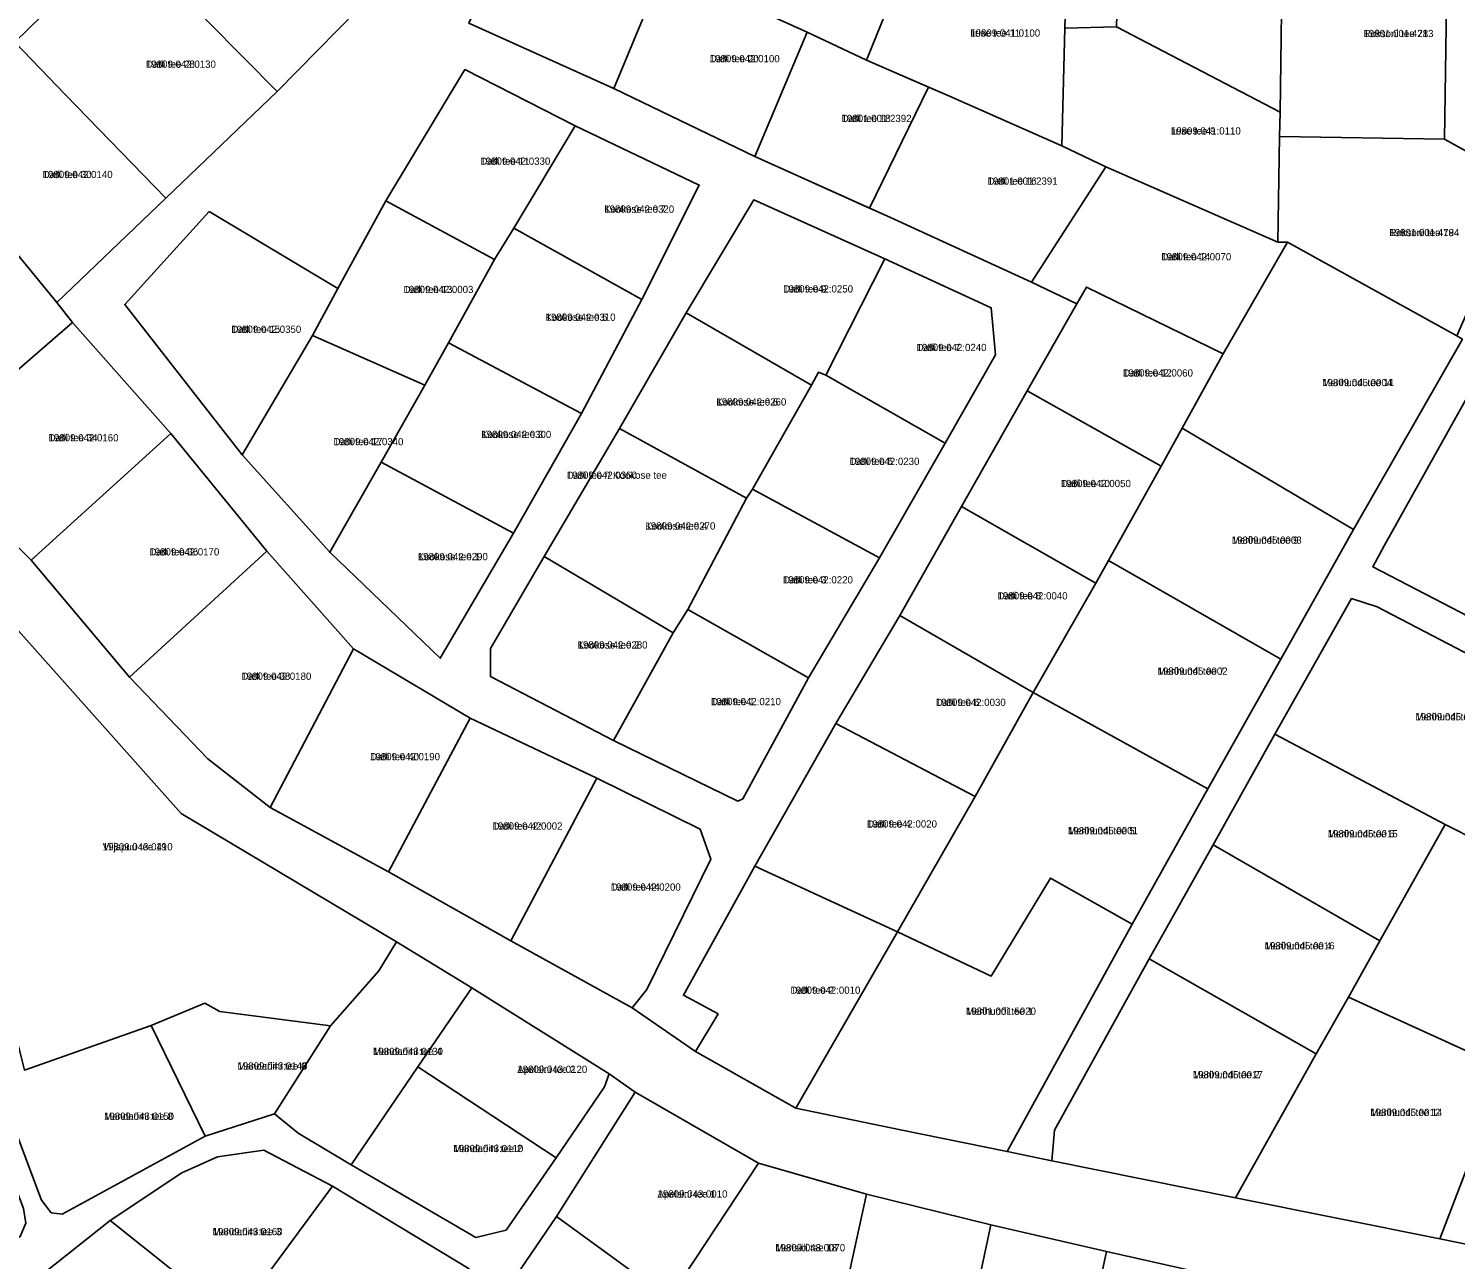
# Model space of a CAD drawing. Extents: x 516875 to 535633, y 6574491 to 6593094.
# Drawn here: x 522001.4 to 522297.3, y 6588394.7 to 6588649.8 of the extents above; entities that cross this region are included whole.
import ezdxf

# ---------------------------------------------------------------- set-up
doc = ezdxf.new("R2010")
doc.units = 0
for name, color, linetype in [('L_AADRESS', 7, 'Continuous'), ('PIIR', 7, 'Continuous'), ('TUNNUS', 7, 'Continuous')]:
    doc.layers.add(name, color=color, linetype=linetype)

msp = doc.modelspace()

# ---------------------------------------------------------------- linework, layer by layer
at = {"layer": 'PIIR'}
for points in [[(522311.5, 6588617.76), (522295, 6588626.88), (522295.65, 6588668.99), (522296.28, 6588711.24), (522296.84, 6588751.11), (522297, 6588762.2), (522296.53, 6588764.76), (522295.97, 6588767.58), (522312.6, 6588763.41)], [(522092.72, 6588650.96), (522122.81, 6588637.37), (522152.05, 6588623.29), (522180.16, 6588610.65), (522209.42, 6588597.23), (522218.77, 6588592.78), (522208.49, 6588574.71), (522194.85, 6588550.77), (522182.06, 6588528.21), (522168.79, 6588505.82), (522152.01, 6588476.24), (522137.21, 6588449.49), (522144.41, 6588445.6), (522139.74, 6588437.81), (522126.56, 6588446.88), (522129.6, 6588450.7), (522142.91, 6588477.69), (522140.67, 6588483.89), (522119.24, 6588494.45), (522092.99, 6588506.9), (522068.78, 6588521.27), (522050.84, 6588541.53), (522030.93, 6588565.87), (522010.56, 6588588.92), (522007.33, 6588593.08), (522029.9, 6588614.7), (522052.99, 6588636.81), (522073.91, 6588658.13)], [(522318.7, 6588510.33), (522281.07, 6588529.99), (522275.77, 6588531.67), (522259.83, 6588503.6), (522247.05, 6588480.62), (522233.76, 6588457.02), (522214.14, 6588421.5), (522213.58, 6588415.18), (522204.36, 6588417.09), (522230.26, 6588464.24), (522245.94, 6588492.24), (522261.06, 6588519.1), (522276.18, 6588546), (522298.73, 6588585.48)], [(522304.64, 6588582.17), (522282.52, 6588542.59), (522280.16, 6588538.3), (522307.29, 6588524.17)], [(521979.37, 6588561.99), (522002.01, 6588539.62), (522022.36, 6588515.38), (522038.59, 6588498.46), (522051.5, 6588488.39), (522076.05, 6588475.08), (522101.42, 6588460.78), (522126.56, 6588446.88), (522139.74, 6588437.81), (522160.54, 6588426.07), (522182.22, 6588421.56), (522204.36, 6588417.09), (522213.58, 6588415.18), (522251.68, 6588407.51), (522294.03, 6588399.01), (522312.11, 6588395.32)], [(522249.57, 6588390.88), (522224.93, 6588396.36), (522200.95, 6588401.92), (522175.18, 6588408.28), (522152.8, 6588414.65), (522127.24, 6588429.4), (522121.82, 6588433.2), (522093.33, 6588451.02), (522077.76, 6588460.57), (522033.06, 6588487.15), (521999.35, 6588525.03)], [(521989.07, 6588394.48), (521999.67, 6588399.47), (522000.86, 6588402.21), (522000.4, 6588405.25), (521989.2, 6588434.61), (521993.17, 6588435.87), (522004.11, 6588406.99), (522006.15, 6588404.36), (522008.43, 6588404.13), (522038.04, 6588420.27), (522052.4, 6588424.89), (522057.35, 6588420.92), (522068.31, 6588414.35), (522094.15, 6588399.29), (522100.45, 6588400.82), (522110.8, 6588415.75), (522120.83, 6588430.51), (522121.82, 6588433.2), (522127.24, 6588429.4), (522110.91, 6588403.64), (522094.05, 6588378.86)], [(522312.11, 6588395.32), (522294.03, 6588399.01), (522307.61, 6588434.31)], [(522092.78, 6588392.77), (522064.48, 6588409.93), (522050.21, 6588417.4), (522040.61, 6588415.96), (522033.23, 6588412.68), (522018.39, 6588402.82), (522004.6, 6588391.87)]]:
    msp.add_lwpolyline(points, dxfattribs=at)
for points in [[(522179.46, 6588682.8), (522189.21, 6588676.93), (522186.29, 6588670.76), (522175.17, 6588643.29), (522162.89, 6588649.04), (522136.11, 6588661.16), (522150.33, 6588694.04)], [(522044.53, 6588691.85), (522073.91, 6588658.13), (522052.99, 6588636.81), (522031.66, 6588658.42), (522021.19, 6588669.13)], [(522113.89, 6588670.89), (522133.15, 6588662.39), (522122.81, 6588637.37), (522092.72, 6588650.96), (522103.83, 6588674.92)], [(522261.43, 6588671.76), (522261.43, 6588668.89), (522260.94, 6588632.46), (522227.01, 6588650.15), (522227.63, 6588672.14)], [(522009.11, 6588636.07), (521998.56, 6588647.03), (522021.19, 6588669.13), (522031.66, 6588658.42), (522052.99, 6588636.81), (522029.9, 6588614.7)], [(522216.73, 6588663.38), (522216.28, 6588649.92), (522215.66, 6588625.53), (522192.41, 6588635.78), (522175.17, 6588643.29), (522186.29, 6588670.76)], [(522261.43, 6588668.89), (522295.65, 6588668.99), (522295, 6588626.88), (522260.83, 6588627.46), (522260.94, 6588632.46)], [(522133.15, 6588662.39), (522136.11, 6588661.16), (522162.89, 6588649.04), (522152.05, 6588623.29), (522122.81, 6588637.37)], [(522175.81, 6588612.61), (522152.05, 6588623.29), (522162.89, 6588649.04), (522175.17, 6588643.29), (522188, 6588637.69)], [(522216.28, 6588649.92), (522227.01, 6588650.15), (522260.94, 6588632.46), (522260.83, 6588627.46), (522260.49, 6588605.57), (522224.82, 6588621.17), (522215.66, 6588625.53)], [(521998.56, 6588647.03), (522009.11, 6588636.07), (522029.9, 6588614.7), (522007.33, 6588593.08), (521988.73, 6588615.62), (521978.84, 6588627.74)], [(522128.62, 6588593.68), (522140.5, 6588617.36), (522114.75, 6588629.65), (522091.87, 6588641.32), (522075.5, 6588614.12), (522065.57, 6588595.93), (522038.89, 6588611.9), (522021.38, 6588592.65), (522045.71, 6588561.48), (522063.9, 6588541.3), (522086.79, 6588519.32), (522101.97, 6588545.23), (522116.12, 6588570.03)], [(522075.5, 6588614.12), (522091.87, 6588641.32), (522114.75, 6588629.65), (522102.04, 6588608.46), (522098.02, 6588601.96)], [(522180.16, 6588610.65), (522175.81, 6588612.61), (522188, 6588637.69), (522192.41, 6588635.78), (522215.66, 6588625.53), (522224.82, 6588621.17), (522209.42, 6588597.23)], [(521979.37, 6588561.99), (521962.07, 6588588.22), (521958.77, 6588593.36), (521953.01, 6588602.36), (521978.84, 6588627.74), (521988.73, 6588615.62), (522007.33, 6588593.08), (522010.56, 6588588.92)], [(522128.62, 6588593.68), (522102.04, 6588608.46), (522114.75, 6588629.65), (522140.5, 6588617.36)], [(522260.83, 6588627.46), (522295, 6588626.88), (522311.5, 6588617.76), (522297.59, 6588586.15), (522262.44, 6588605.57), (522260.49, 6588605.57)], [(522249.14, 6588582.38), (522220.77, 6588596.25), (522218.77, 6588592.78), (522209.42, 6588597.23), (522224.82, 6588621.17), (522260.49, 6588605.57), (522262.44, 6588605.57)], [(522098.02, 6588601.96), (522088.52, 6588584.69), (522083.6, 6588575.89), (522060.31, 6588586.24), (522065.57, 6588595.93), (522075.5, 6588614.12)], [(522201.95, 6588582.23), (522201.04, 6588591.95), (522178.98, 6588602.08), (522151.8, 6588614.3), (522137.81, 6588590.88), (522123.98, 6588566.92), (522108.36, 6588540.42), (522097.25, 6588521.32), (522097.25, 6588515.54), (522122.7, 6588502.26), (522148.52, 6588489.71), (522149.56, 6588490.16), (522163.15, 6588515.29), (522177.86, 6588540.13), (522191.49, 6588563.87)], [(522151.8, 6588614.3), (522178.98, 6588602.08), (522166.73, 6588578), (522165.24, 6588578.62), (522163.77, 6588575.93), (522137.81, 6588590.88)], [(522060.31, 6588586.24), (522045.71, 6588561.48), (522021.38, 6588592.65), (522038.89, 6588611.9), (522065.57, 6588595.93)], [(522116.12, 6588570.03), (522088.52, 6588584.69), (522098.02, 6588601.96), (522102.04, 6588608.46), (522128.62, 6588593.68)], [(522298.73, 6588585.48), (522276.18, 6588546), (522240.62, 6588567), (522249.14, 6588582.38), (522262.44, 6588605.57), (522297.59, 6588586.15)], [(522201.95, 6588582.23), (522191.49, 6588563.87), (522166.73, 6588578), (522178.98, 6588602.08), (522201.04, 6588591.95)], [(522236.27, 6588559.15), (522208.49, 6588574.71), (522218.77, 6588592.78), (522220.77, 6588596.25), (522249.14, 6588582.38), (522240.62, 6588567)], [(522137.81, 6588590.88), (522163.77, 6588575.93), (522151.55, 6588554.36), (522150.32, 6588552.51), (522123.98, 6588566.92)], [(522002.01, 6588539.62), (521979.37, 6588561.99), (522010.56, 6588588.92), (522030.93, 6588565.87)], [(522045.71, 6588561.48), (522060.31, 6588586.24), (522083.6, 6588575.89), (522074.54, 6588559.95), (522063.9, 6588541.3)], [(522101.97, 6588545.23), (522074.54, 6588559.95), (522083.6, 6588575.89), (522088.52, 6588584.69), (522116.12, 6588570.03)], [(522330.41, 6588567.7), (522307.29, 6588524.17), (522280.16, 6588538.3), (522282.52, 6588542.59), (522304.64, 6588582.17)], [(522177.86, 6588540.13), (522151.55, 6588554.36), (522163.77, 6588575.93), (522165.24, 6588578.62), (522166.73, 6588578), (522191.49, 6588563.87)], [(522236.27, 6588559.15), (522225.37, 6588539.57), (522222.75, 6588534.87), (522194.85, 6588550.77), (522208.49, 6588574.71)], [(522002.01, 6588539.62), (522030.93, 6588565.87), (522050.84, 6588541.53), (522022.36, 6588515.38)], [(522123.98, 6588566.92), (522150.32, 6588552.51), (522138.16, 6588529.45), (522135.1, 6588524.59), (522108.36, 6588540.42)], [(522276.18, 6588546), (522261.06, 6588519.1), (522225.37, 6588539.57), (522236.27, 6588559.15), (522240.62, 6588567)], [(522086.79, 6588519.32), (522063.9, 6588541.3), (522074.54, 6588559.95), (522101.97, 6588545.23)], [(522163.15, 6588515.29), (522138.16, 6588529.45), (522150.32, 6588552.51), (522151.55, 6588554.36), (522177.86, 6588540.13)], [(522222.75, 6588534.87), (522209.74, 6588512.25), (522182.06, 6588528.21), (522194.85, 6588550.77)], [(522051.5, 6588488.39), (522038.59, 6588498.46), (522022.36, 6588515.38), (522050.84, 6588541.53), (522068.78, 6588521.27)], [(522097.25, 6588515.54), (522097.25, 6588521.32), (522108.36, 6588540.42), (522135.1, 6588524.59), (522122.7, 6588502.26)], [(522261.06, 6588519.1), (522245.94, 6588492.24), (522209.74, 6588512.25), (522222.75, 6588534.87), (522225.37, 6588539.57)], [(522281.07, 6588529.99), (522318.7, 6588510.33), (522302.29, 6588481.25), (522295.19, 6588484.85), (522259.83, 6588503.6), (522275.77, 6588531.67)], [(522149.56, 6588490.16), (522148.52, 6588489.71), (522122.7, 6588502.26), (522135.1, 6588524.59), (522138.16, 6588529.45), (522163.15, 6588515.29)], [(522209.74, 6588512.25), (522197.73, 6588490.64), (522168.79, 6588505.82), (522182.06, 6588528.21)], [(521999.54, 6588438.13), (521985.98, 6588485.52), (521981.86, 6588503.81), (521999.35, 6588525.03), (522033.06, 6588487.15), (522077.76, 6588460.57), (522074.08, 6588454.51), (522064.03, 6588443.14), (522041.13, 6588446.11), (522038.02, 6588447.86), (522026.84, 6588443.19), (522000.61, 6588433.97)], [(522051.5, 6588488.39), (522068.78, 6588521.27), (522092.99, 6588506.9), (522076.05, 6588475.08)], [(522245.94, 6588492.24), (522230.26, 6588464.24), (522213.32, 6588473.76), (522201.01, 6588453.43), (522181.6, 6588462.64), (522197.73, 6588490.64), (522209.74, 6588512.25)], [(522092.99, 6588506.9), (522119.24, 6588494.45), (522101.42, 6588460.78), (522076.05, 6588475.08)], [(522181.6, 6588462.64), (522152.01, 6588476.24), (522168.79, 6588505.82), (522197.73, 6588490.64)], [(522259.83, 6588503.6), (522295.19, 6588484.85), (522281.63, 6588460.79), (522247.05, 6588480.62)], [(522101.42, 6588460.78), (522119.24, 6588494.45), (522140.67, 6588483.89), (522142.91, 6588477.69), (522129.6, 6588450.7), (522126.56, 6588446.88)], [(522302.29, 6588481.25), (522321.62, 6588470.82), (522307.61, 6588434.31), (522275.1, 6588449.07), (522281.63, 6588460.79), (522295.19, 6588484.85)], [(522281.63, 6588460.79), (522275.1, 6588449.07), (522268.44, 6588437.33), (522233.76, 6588457.02), (522247.05, 6588480.62)], [(522181.6, 6588462.64), (522160.54, 6588426.07), (522139.74, 6588437.81), (522144.41, 6588445.6), (522137.21, 6588449.49), (522152.01, 6588476.24)], [(522160.54, 6588426.07), (522181.6, 6588462.64), (522201.01, 6588453.43), (522213.32, 6588473.76), (522230.26, 6588464.24), (522204.36, 6588417.09), (522182.24, 6588421.59)], [(522057.35, 6588420.92), (522052.4, 6588424.89), (522064.03, 6588443.14), (522074.08, 6588454.51), (522077.76, 6588460.57), (522093.33, 6588451.02), (522082.12, 6588434.65), (522068.31, 6588414.35)], [(522214.14, 6588421.5), (522233.76, 6588457.02), (522268.44, 6588437.33), (522251.68, 6588407.51), (522213.58, 6588415.18)], [(522121.82, 6588433.2), (522120.83, 6588430.51), (522110.8, 6588415.75), (522082.12, 6588434.65), (522093.33, 6588451.02)], [(522026.84, 6588443.19), (522038.02, 6588447.86), (522041.13, 6588446.11), (522064.03, 6588443.14), (522052.4, 6588424.89), (522038.04, 6588420.27)], [(522307.61, 6588434.31), (522294.03, 6588399.01), (522251.68, 6588407.51), (522268.44, 6588437.33), (522275.1, 6588449.07)], [(522006.15, 6588404.36), (522004.11, 6588406.99), (521993.17, 6588435.87), (521999.54, 6588438.13), (522000.61, 6588433.97), (522026.84, 6588443.19), (522038.04, 6588420.27), (522008.43, 6588404.13)], [(522110.8, 6588415.75), (522100.45, 6588400.82), (522094.15, 6588399.29), (522068.31, 6588414.35), (522082.12, 6588434.65)], [(522152.8, 6588414.65), (522137.34, 6588391.3), (522134.27, 6588386.61), (522110.91, 6588403.64), (522127.24, 6588429.4)], [(522033.23, 6588412.68), (522040.61, 6588415.96), (522050.21, 6588417.4), (522064.48, 6588409.93), (522050.26, 6588390.69), (522044.38, 6588382.1), (522018.39, 6588402.82)], [(522175.18, 6588408.28), (522168.11, 6588376.06), (522166.24, 6588372.75), (522137.34, 6588391.3), (522152.8, 6588414.65)], [(522064.48, 6588409.93), (522092.78, 6588392.77), (522093.7, 6588390.23), (522080.13, 6588370.27), (522050.26, 6588390.69)], [(522200.95, 6588401.92), (522194.06, 6588369.42), (522168.11, 6588376.06), (522175.18, 6588408.28)], [(522006.88, 6588371.24), (522008.43, 6588373.57), (522002.04, 6588377.52), (522008, 6588386.5), (522004.6, 6588391.87), (522018.39, 6588402.82), (522044.38, 6588382.1), (522038.94, 6588374.15), (522028.11, 6588358.8), (522027.34, 6588359.31)], [(522094.05, 6588378.86), (522110.91, 6588403.64), (522134.27, 6588386.61), (522125.12, 6588372.66), (522117.54, 6588361.73)], [(522224.93, 6588396.36), (522218.17, 6588364.58), (522194.06, 6588369.42), (522200.95, 6588401.92)], [(522249.57, 6588390.88), (522243.06, 6588359.61), (522218.17, 6588364.58), (522224.93, 6588396.36)]]:
    msp.add_lwpolyline(points, close=True, dxfattribs=at)

# ---------------------------------------------------------------- texts
at = {"layer": 'L_AADRESS'}
for s, p in [('Iirise tee 11', (522196.69, 6588648.15)), ('Roksoni tee 21', (522278.24, 6588648.05)), ('Datli tee 28', (522025.78, 6588641.69)), ('Datli tee 20', (522142.68, 6588642.84)), ('Datli tee 18', (522170.02, 6588630.45)), ('Iirise tee 9', (522238.28, 6588627.86)), ('Datli tee 11', (522095.12, 6588621.59)), ('Datli tee 30', (522004.37, 6588618.83)), ('Datli tee 16', (522200.3, 6588617.46)), ('Kookose tee 7', (522120.8, 6588611.66)), ('Roksoni tee 19', (522283.59, 6588606.8)), ('Datli tee 14', (522236.3, 6588601.78)), ('Datli tee 13', (522079.17, 6588595)), ('Datli tee 9', (522157.89, 6588595.12)), ('Kookose tee 5', (522108.65, 6588589.25)), ('Datli tee 15', (522043.48, 6588586.75)), ('Datli tee 7', (522185.57, 6588582.98)), ('Datli tee 12', (522228.37, 6588577.7)), ('Merihundi tee 11', (522269.67, 6588575.71)), ('Kookose tee 6', (522144.05, 6588571.7)), ('Datli tee 34', (522005.59, 6588564.27)), ('Kookose tee 3', (522095.31, 6588564.96)), ('Datli tee 17', (522064.66, 6588563.47)), ('Datli tee 5', (522171.65, 6588559.38)), ('Datli tee // Kookose tee', (522113.05, 6588556.51)), ('Datli tee 10', (522215.49, 6588554.79)), ('Kookose tee 4', (522129.34, 6588545.99)), ('Datli tee 36', (522026.49, 6588540.62)), ('Merihundi tee 9', (522250.91, 6588543.05)), ('Kookose tee 1', (522082.16, 6588539.63)), ('Datli tee 3', (522157.86, 6588534.82)), ('Datli tee 8', (522202.37, 6588531.51)), ('Kookose tee 2', (522115.28, 6588521.34)), ('Datli tee 38', (522045.57, 6588514.85)), ('Merihundi tee 7', (522235.55, 6588515.9)), ('Datli tee 1', (522142.93, 6588509.59)), ('Datli tee 6', (522189.55, 6588509.43)), ('Merihundi tee 8', (522288.99, 6588506.46)), ('Datli tee 40', (522072.25, 6588498.18)), ('Datli tee 4', (522175.29, 6588484.23)), ('Datli tee 42', (522097.64, 6588483.8)), ('Merihundi tee 5', (522216.96, 6588482.84)), ('Merihundi tee 6', (522270.81, 6588482.2)), ('Viljapuu tee 19', (522016.81, 6588479.5)), ('Datli tee 44', (522122.16, 6588471.16)), ('Merihundi tee 4', (522257.74, 6588458.98)), ('Datli tee 2', (522159.41, 6588449.78)), ('Merihundi tee 1', (522195.81, 6588445.43)), ('Mandariini tee 4', (522072.86, 6588437.09)), ('Mandariini tee 6', (522044.77, 6588434.07)), ('Apelsini tee 2', (522102.78, 6588433.38)), ('Merihundi tee 2', (522242.84, 6588432.27)), ('Mandariini tee 8', (522017.09, 6588423.66)), ('Merihundi tee 14', (522279.64, 6588424.45)), ('Mandariini tee 2', (522089.52, 6588416.97)), ('Apelsini tee 1', (522131.85, 6588407.55)), ('Mandariini tee 3', (522039.6, 6588399.75)), ('Merisiili tee 18', (522156.26, 6588396.41))]:
    msp.add_text(s, height=1.5, dxfattribs=at).set_placement(p)
at = {"layer": 'TUNNUS'}
for s, p in [('19809:041:0100', (522196.69, 6588648.15)), ('19801:001:4783', (522278.24, 6588648.05)), ('19809:042:0130', (522025.78, 6588641.69)), ('19809:042:0100', (522142.68, 6588642.84)), ('19801:001:2392', (522170.02, 6588630.45)), ('19809:041:0110', (522238.28, 6588627.86)), ('19809:042:0330', (522095.12, 6588621.59)), ('19809:042:0140', (522004.37, 6588618.83)), ('19801:001:2391', (522200.3, 6588617.46)), ('19809:042:0320', (522120.8, 6588611.66)), ('19801:001:4784', (522283.59, 6588606.8)), ('19809:042:0070', (522236.3, 6588601.78)), ('19809:042:0003', (522079.17, 6588595)), ('19809:042:0250', (522157.89, 6588595.12)), ('19809:042:0310', (522108.65, 6588589.25)), ('19809:042:0350', (522043.48, 6588586.75)), ('19809:042:0240', (522185.57, 6588582.98)), ('19809:042:0060', (522228.37, 6588577.7)), ('19809:045:0004', (522269.67, 6588575.71)), ('19809:042:0260', (522144.05, 6588571.7)), ('19809:042:0160', (522005.59, 6588564.27)), ('19809:042:0300', (522095.31, 6588564.96)), ('19809:042:0340', (522064.66, 6588563.47)), ('19809:042:0230', (522171.65, 6588559.38)), ('19809:042:0360', (522113.05, 6588556.51)), ('19809:042:0050', (522215.49, 6588554.79)), ('19809:042:0270', (522129.34, 6588545.99)), ('19809:042:0170', (522026.49, 6588540.62)), ('19809:045:0003', (522250.91, 6588543.05)), ('19809:042:0290', (522082.16, 6588539.63)), ('19809:042:0220', (522157.86, 6588534.82)), ('19809:042:0040', (522202.37, 6588531.51)), ('19809:042:0280', (522115.28, 6588521.34)), ('19809:042:0180', (522045.57, 6588514.85)), ('19809:045:0002', (522235.55, 6588515.9)), ('19809:042:0210', (522142.93, 6588509.59)), ('19809:042:0030', (522189.55, 6588509.43)), ('19809:045:0014', (522288.99, 6588506.46)), ('19809:042:0190', (522072.25, 6588498.18)), ('19809:042:0020', (522175.29, 6588484.23)), ('19809:042:0002', (522097.64, 6588483.8)), ('19809:045:0001', (522216.96, 6588482.84)), ('19809:045:0015', (522270.81, 6588482.2)), ('19809:043:0410', (522016.81, 6588479.5)), ('19809:042:0200', (522122.16, 6588471.16)), ('19809:045:0016', (522257.74, 6588458.98)), ('19809:042:0010', (522159.41, 6588449.78)), ('19801:001:5020', (522195.81, 6588445.43)), ('19809:043:0130', (522072.86, 6588437.09)), ('19809:043:0140', (522044.77, 6588434.07)), ('19809:043:0120', (522102.78, 6588433.38)), ('19809:045:0017', (522242.84, 6588432.27)), ('19809:043:0150', (522017.09, 6588423.66)), ('19809:045:0012', (522279.64, 6588424.45)), ('19809:043:0110', (522089.52, 6588416.97)), ('19809:043:0010', (522131.85, 6588407.55)), ('19809:043:0160', (522039.6, 6588399.75)), ('19809:048:0070', (522156.26, 6588396.41))]:
    msp.add_text(s, height=1.5, dxfattribs=at).set_placement(p)

doc.saveas('drawing.dxf')
